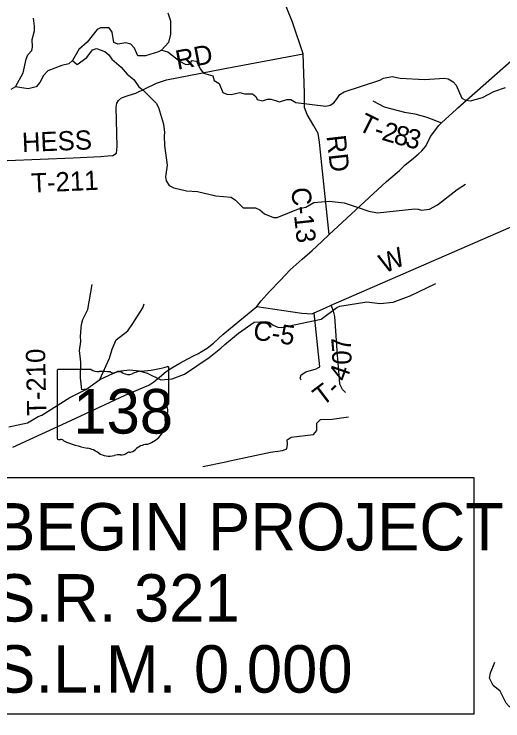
# Model space of a CAD drawing. Extents: x 0 to 34, y 0 to 22.
# Drawn here: x 4.877 to 6.32, y 18.054 to 20.142 of the extents above; entities that cross this region are included whole.
import ezdxf

# ---------------------------------------------------------------- set-up
doc = ezdxf.new("R2010")
doc.units = 0
for name, color, linetype in [('Default', 7, 'Continuous'), ('GM_X_County_Road', 7, 'Continuous'), ('GM_X_County_Road_Text', 7, 'Continuous'), ('GM_X_Minor_River', 7, 'Continuous'), ('GM_X_State_Location', 7, 'Continuous'), ('GM_X_State_Route', 7, 'Continuous'), ('GM_X_State_Shield', 7, 'Continuous'), ('GM_X_Township_Road', 7, 'Continuous'), ('GM_X_Township_Road_Text', 7, 'Continuous')]:
    doc.layers.add(name, color=color, linetype=linetype)

msp = doc.modelspace()

# ---------------------------------------------------------------- linework, layer by layer
at = {"layer": 'Default'}
msp.add_lwpolyline([(4.7876, 18.7727), (6.235, 18.7727), (6.235, 18.073), (4.7876, 18.073)], close=True, dxfattribs=at)
at = {"layer": 'GM_X_County_Road'}
for points in [[(5.8078, 19.4902), (5.7818, 19.7334), (5.7792, 19.7638), (5.7747, 19.7893), (5.7622, 19.8116), (5.7427, 19.8449), (5.7343, 19.866), (5.7346, 19.9081), (5.731, 20.0244), (5.6988, 20.118), (5.681, 20.1639), (5.6577, 20.2896), (5.6304, 20.4028), (5.5849, 20.5608), (5.5348, 20.7388), (5.516, 20.7887), (5.4308, 20.8798), (5.4141, 20.8852), (5.3337, 20.8941)], [(5.5935, 19.2775), (5.7264, 19.2583), (5.7427, 19.2576), (5.7571, 19.2562), (5.7629, 19.2588), (5.7962, 19.2737), (5.8137, 19.2814), (6.4281, 19.5499), (6.7192, 19.6766), (7.0264, 19.8102), (7.0346, 19.8137), (7.0373, 19.8148)]]:
    msp.add_lwpolyline(points, dxfattribs=at)
at = {"layer": 'GM_X_Minor_River'}
for points in [[(4.8809, 19.9272), (4.9036, 19.9677), (4.9131, 20.0086), (4.9182, 20.021), (4.9294, 20.0337), (4.9319, 20.0443), (4.9308, 20.0667), (4.9376, 20.092), (4.9371, 20.106), (4.9345, 20.1296)], [(5.3311, 20.1452), (5.3391, 20.1223), (5.3392, 20.0825), (5.3334, 20.0575), (5.3129, 20.0355), (5.3034, 20.0307), (5.2652, 20.0181), (5.2421, 20.0185), (5.233, 20.041), (5.2218, 20.0526), (5.2067, 20.057), (5.1831, 20.0525), (5.1715, 20.0576), (5.1663, 20.0881), (5.1578, 20.1007), (5.1324, 20.1012), (5.1224, 20.096), (5.0926, 20.0586), (5.0683, 20.037), (5.0495, 20.0047), (5.0384, 19.9947), (5.0186, 19.9897), (4.9773, 19.9741)], [(5.0495, 20.0047), (5.0634, 19.9931), (5.0922, 20.0138), (5.1089, 20.0359), (5.1207, 20.0403), (5.1448, 20.0308), (5.1572, 20.0211), (5.1661, 20.0084), (5.193, 19.9848), (5.2108, 19.964), (5.2306, 19.9489), (5.2451, 19.927), (5.2582, 19.9173), (5.2966, 19.8783), (5.3039, 19.8661), (5.3179, 19.8169), (5.3209, 19.7922), (5.3207, 19.7823), (5.3209, 19.7531), (5.3287, 19.6949), (5.3239, 19.6609), (5.326, 19.6487), (5.3349, 19.6356), (5.3488, 19.6282), (5.3862, 19.6196), (5.4187, 19.6179), (5.4724, 19.6052), (5.5186, 19.6006), (5.5313, 19.5917), (5.5533, 19.5689), (5.5901, 19.5698), (5.6025, 19.5639), (5.6164, 19.5515), (5.6427, 19.5408), (5.6537, 19.5406), (5.7167, 19.5661), (5.7289, 19.5697), (5.7388, 19.571), (5.7622, 19.585), (5.807, 19.5892), (5.8521, 19.5839), (5.8898, 19.5715), (5.9248, 19.5595), (5.9502, 19.5549), (6.0604, 19.5666), (6.0702, 19.5649), (6.0804, 19.5629), (6.104, 19.5651), (6.1269, 19.578), (6.185, 19.6233), (6.2103, 19.6395)], [(5.3129, 20.0355), (5.3314, 20.0306), (5.3673, 20.0012), (5.382, 19.9937), (5.3934, 19.9928), (5.403, 20.0047), (5.4159, 20.003), (5.4265, 19.9804), (5.4365, 19.9674), (5.4637, 19.9589), (5.4684, 19.946), (5.4823, 19.9362), (5.4932, 19.9102), (5.5056, 19.9051), (5.5178, 19.9045), (5.544, 19.9098), (5.5576, 19.9057), (5.5807, 19.9057), (5.5909, 19.8987), (5.5952, 19.8891), (5.6107, 19.8855), (5.6252, 19.8905), (5.6355, 19.8903), (5.6491, 19.8867), (5.6604, 19.8823), (5.6825, 19.8892), (5.6946, 19.889), (5.7093, 19.8804), (5.7975, 19.8701), (5.8108, 19.8722), (5.8208, 19.8792), (5.8308, 19.8923), (5.8386, 19.9043), (5.8513, 19.9124), (5.9573, 19.9467), (5.9677, 19.9525), (5.9935, 19.9574), (6.0173, 19.9521), (6.089, 19.9486), (6.1478, 19.9525), (6.1592, 19.95), (6.1738, 19.9418), (6.1827, 19.9318), (6.1991, 19.8935), (6.21, 19.8877), (6.2248, 19.8851), (6.2606, 19.8951), (6.2932, 19.9132), (6.3279, 19.9251)], [(4.9773, 19.9741), (4.9642, 19.9603), (4.9528, 19.9392), (4.942, 19.9269), (4.9191, 19.9212), (4.8809, 19.9272), (4.8679, 19.919)], [(4.8614, 18.9226), (4.917, 18.9342), (4.9487, 18.9526), (4.9587, 18.957), (5.0415, 19.0091), (5.0912, 19.0336), (5.1308, 19.0625), (5.1836, 19.087), (5.2193, 19.091), (5.2465, 19.0875), (5.2699, 19.0806), (5.3102, 19.0614), (5.344, 19.0642), (5.3803, 19.078), (5.4532, 19.1276), (5.4878, 19.1547), (5.4997, 19.1651), (5.5401, 19.1989), (5.5858, 19.2315), (5.62, 19.2339), (5.6302, 19.2319), (5.6422, 19.2222), (5.6561, 19.2166), (5.6667, 19.2161), (5.7839, 19.2402), (5.8297, 19.2751), (5.8392, 19.2791), (5.9191, 19.2914), (5.9585, 19.2869), (5.9961, 19.2904), (6.0358, 19.3057), (6.0465, 19.3097), (6.1226, 19.3459)], [(5.0912, 19.0336), (5.0772, 19.0316), (5.0732, 19.0666), (5.0744, 19.1136), (5.0701, 19.1482), (5.0739, 19.1746), (5.0731, 19.1906), (5.0763, 19.2251), (5.08, 19.2394), (5.0945, 19.2691), (5.1079, 19.3429)], [(5.1308, 19.0625), (5.1592, 19.1254), (5.1665, 19.1522), (5.1783, 19.1797), (5.2129, 19.2056), (5.2277, 19.2274), (5.2573, 19.2739), (5.2617, 19.2856)], [(5.4347, 18.8047), (5.5025, 18.8191), (5.5139, 18.8219), (5.6342, 18.8475), (5.6699, 18.8526), (5.6829, 18.8577), (5.6847, 18.8713), (5.683, 18.8835), (5.6949, 18.892), (5.7614, 18.9), (5.7707, 18.9119), (5.7707, 18.9332), (5.7819, 18.9444), (5.816, 18.9449), (5.8643, 18.952)], [(6.4105, 18.0536), (6.339, 18.0956), (6.3304, 18.1063), (6.3119, 18.1414), (6.2913, 18.1584), (6.2809, 18.1802), (6.2834, 18.1953), (6.2964, 18.2274)]]:
    msp.add_lwpolyline(points, dxfattribs=at)
at = {"layer": 'GM_X_State_Route'}
for points in [[(6.2956, 19.9604), (6.4341, 20.0826), (6.4833, 20.1299), (6.5043, 20.1498), (6.6785, 20.3128), (6.6982, 20.3384), (6.8371, 20.4739), (6.8679, 20.505), (6.9295, 20.564)], [(6.1837, 19.8609), (6.1874, 19.8643), (6.2956, 19.9604)], [(4.8738, 18.862), (5.0452, 18.9408), (5.2048, 19.0161), (5.2632, 19.0403), (5.2755, 19.0456), (5.2902, 19.0555), (5.3069, 19.0694), (5.3263, 19.0856), (5.3429, 19.0965), (5.3661, 19.1103), (5.3903, 19.1229), (5.4092, 19.1327), (5.4219, 19.1391), (5.4279, 19.1426), (5.4474, 19.1544), (5.4657, 19.1692), (5.494, 19.1948), (5.5935, 19.2775), (5.6072, 19.2942), (5.6312, 19.3224), (5.664, 19.3557), (5.6921, 19.3864), (5.7275, 19.4173), (5.7575, 19.4434), (5.7863, 19.4696), (5.8078, 19.4902), (5.9765, 19.6473), (6.0149, 19.6796), (6.0317, 19.6963), (6.0507, 19.7113), (6.0698, 19.7282), (6.0815, 19.7382), (6.0932, 19.7519), (6.1065, 19.78), (6.131, 19.8123), (6.1394, 19.8201), (6.1837, 19.8609)]]:
    msp.add_lwpolyline(points, dxfattribs=at)
at = {"layer": 'GM_X_State_Shield'}
for p, q in [((5.0047, 19.0884), (5.0047, 18.8882)), ((5.1045, 19.0918), (5.008, 19.0918)), ((5.3343, 18.9921), (5.3343, 19.0968)), ((5.3343, 18.9921), (5.3343, 18.9921))]:
    msp.add_line(p, q, dxfattribs=at)
for centre, major_axis, start_param, end_param in [((5.0085, 19.0888), (0.00382, 0), 1.712693, 3.28349), ((5.1275, 19.115), (0.037, 0), 4.042523, 4.731795), ((5.1397, 18.9794), (0.133, 0), 1.404758, 1.657858), ((5.1856, 19.0667), (0.0222, 0), 0.950623, 2.079405), ((5.2615, 19.0307), (0.0703, 0), 1.699011, 2.107814), ((5.2169, 19.3646), (0.3495, 0), 4.814394, 5.042369), ((5.3306, 19.0972), (0.00367, 0), 6.141152, 7.989035), ((5.1699, 19.0898), (0.0107, 0), 3.836095, 5.185415), ((5.2143, 19.0984), (0.0267, 0), 4.081561, 5.145723), ((5.3334, 18.9844), (0.00568, 0), 1.883978, 3.671073), ((5.2973, 18.9712), (0.0341, 0), 5.934695, 6.695948), ((5.3304, 18.9917), (0.00393, 0), 5.05454, 6.418171), ((5.3474, 18.9483), (0.0248, 0), 2.387724, 3.262537), ((5.2365, 18.9349), (0.0874, 0), 5.101752, 6.440018), ((5.0085, 18.8878), (0.00385, 0), 3.00124, 4.508301), ((5.0091, 18.9083), (0.0294, 0), 4.665946, 4.897461), ((5.0151, 18.8767), (0.0106, 0), 0.519207, 1.627899), ((5.1489, 19.0565), (0.2524, 0), 4.195997, 4.488961), ((5.0737, 18.7983), (0.079, 0), 0.823519, 1.323587), ((5.2127, 18.8688), (0.0282, 0), 4.937069, 5.64225), ((5.2733, 18.8321), (0.0479, 0), 1.647645, 2.488434), ((5.1591, 18.8757), (0.0501, 0), 4.026481, 4.996735), ((5.1881, 18.8065), (0.0412, 0), 1.495662, 1.94098), ((5.1917, 18.8607), (0.0267, 0), 4.691044, 5.507374), ((5.2159, 18.8413), (0.00752, 0), 1.147584, 2.315152)]:
    msp.add_ellipse(centre, major_axis=major_axis, ratio=0.8, start_param=start_param, end_param=end_param, dxfattribs=at)
at = {"layer": 'GM_X_Township_Road'}
for points in [[(4.8567, 19.7096), (5.0517, 19.7173), (5.1331, 19.7208), (5.154, 19.7227), (5.1685, 19.7243), (5.1792, 19.731), (5.1811, 19.7507), (5.1785, 19.8666), (5.1803, 19.8783), (5.1857, 19.8862), (5.1946, 19.8944), (5.2141, 19.9009), (5.2366, 19.9077), (5.263, 19.9205), (5.2979, 19.9374), (5.327, 19.9475), (5.4943, 19.9803), (5.731, 20.0244)], [(5.9362, 19.8857), (5.9699, 19.8682), (6.0301, 19.8524), (6.06, 19.8471), (6.0956, 19.8373), (6.1394, 19.8201)], [(5.8557, 19.0234), (5.8472, 19.0329), (5.843, 19.04), (5.8392, 19.0479), (5.8376, 19.0631), (5.8321, 19.1339), (5.8301, 19.1623), (5.8241, 19.2484), (5.8205, 19.2637), (5.8137, 19.2814)], [(5.7253, 19.0604), (5.7216, 19.0658), (5.7248, 19.0764), (5.739, 19.0852), (5.7687, 19.0935), (5.776, 19.0971), (5.7795, 19.0993), (5.7629, 19.2588)]]:
    msp.add_lwpolyline(points, dxfattribs=at)

# ---------------------------------------------------------------- texts
at = {"layer": 'Default'}
for s, p in [('BEGIN PROJECT', (4.8152, 18.557)), ('S.R. 321', (4.8152, 18.347)), ('S.L.M. 0.000', (4.8152, 18.137))]:
    msp.add_text(s, height=0.14, dxfattribs=at).set_placement(p)
at = {"layer": 'GM_X_County_Road_Text'}
for s, height, rotation, p in [('RD', 0.05682, 276.3954, (5.7995, 19.7815)), ('C-13', 0.05682, 276.1885, (5.695, 19.6269)), ('W', 0.0568, 23.0102, (5.9702, 19.3748)), ('C-5', 0.05682, 351.7416, (5.5806, 19.1807))]:
    msp.add_text(s, height=height, rotation=rotation, dxfattribs=at).set_placement(p)
at = {"layer": 'GM_X_State_Location'}
msp.add_text('138', height=0.000189, rotation=0, dxfattribs=at).set_placement((5.0989, 18.9612))
for s in ['s', 'r']:
    msp.add_text(s, height=0.000189, dxfattribs=at).set_placement((5.1658, 18.975))
at = {"layer": 'GM_X_State_Shield'}
msp.add_text('138', height=0.13184, dxfattribs=at).set_placement((5.0523, 18.9023))
at = {"layer": 'GM_X_Township_Road_Text'}
for s, height, rotation, p in [('RD', 0.05682, 10.9225, (5.3597, 19.977)), ('T', 0.0568, 333.8077, (5.8896, 19.8005)), ('2', 0.0568, 343.5686, (5.9598, 19.7709)), ('HESS', 0.05682, 2.2456, (4.9014, 19.7341)), ('-', 0.0568, 342.4822, (5.9364, 19.7782)), ('8', 0.0568, 345.0336, (5.9949, 19.7605)), ('3', 0.0568, 345.4733, (6.0291, 19.7514)), ('T-211', 0.05682, 2.5269, (4.9291, 19.6141)), ('7', 0.0568, 94.9847, (5.8734, 19.147)), ('T-210', 0.05682, 91.1232, (4.9725, 18.9554)), ('0', 0.0568, 89.0439, (5.873, 19.1055)), ('4', 0.0568, 70.964, (5.8583, 19.0533)), ('T', 0.0568, 37.2702, (5.787, 18.9818)), ('-', 0.0568, 45.4343, (5.8274, 19.0134))]:
    msp.add_text(s, height=height, rotation=rotation, dxfattribs=at).set_placement(p)

doc.saveas('drawing.dxf')
